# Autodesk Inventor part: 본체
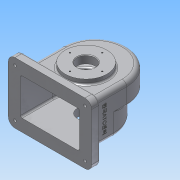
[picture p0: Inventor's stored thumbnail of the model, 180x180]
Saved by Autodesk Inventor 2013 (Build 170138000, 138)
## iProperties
Created: 2017-11
Part Number: 본체
Material: 알루미늄 6061
Document SubType Name: Modeling
Designer: Administrator
Density: 2.71 g/cm^3
Mass: 1079.49 g
Surface Area: 1182.07 cm^2
Volume: 398.335 cm^3
Author: Administrator
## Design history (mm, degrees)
sketch "스케치1"
  geometry: L1 (-58, 0)-(-58, -80); L2 (-58, -80)-(58, -80); L3 (58, -80)-(58, 0); A1 r 58 centre (0, 0) between (58, 0) and (-58, 0); 1 further point
  constraints: 6 end point, 2 point on circle, 2 tangent, 1 centre point, 1 coincident, 1 parallel, 1 perpendicular, 1 vertical
  dimensions: "d0" = 116 diameter of A1; "d1" = 80 distance from line of L2 A1.centre
extrude "돌출1" new body sketch "스케치1" distance "d2" = 38; taper "d3" = 0 deg
sketch "스케치2"
  geometry: L1 (-58, 0)-(-58, -80) reference; L2 (-58, -80)-(58, -80) reference; L3 (58, -80)-(58, 0) reference; L4 (-58, -23)-(-58, -80); L5 (58, -80)-(58, -23); L6 (58, -80)-(-58, -80); A1 r 58 centre (0, 0) between (58, 0) and (-58, 0) reference; A2 r 58 centre (0, -23) between (58, -23) and (-58, -23)
  constraints: 6 end point, 3 collinear, 2 point on circle, 2 point on line, 1 centre point, 1 vertical alignment
  dimensions: "d4" = 116 diameter of A2; "d5" = 57 distance from line of L2 A2.centre
extrude "돌출2" join sketch "스케치2" distance "d6" = 38; taper "d7" = 0 deg
feature "쉘1" dims "d10" = 5
fillet "모깎기3" dims "d11" = 8
fillet "모깎기4" dims "d12" = 3
sketch "스케치3"
  geometry: L1 (108, -8)-(108, -68) reference; L2 (0, 0)-(100, 0) reference; L3 (-8, -8)-(-8, -68) reference; L4 (100, -76)-(0, -76) reference; L5 (-25, 17)-(125, 17); L6 (125, 17)-(125, -93); L7 (125, -93)-(-25, -93); L8 (-25, -93)-(-25, 17); L9 (-25, 17)-(125, -93); L10 (125, 17)-(-25, -93); A1 r 8 centre (100, -68) between (100, -76) and (108, -68) reference; A2 r 8 centre (100, -8) between (108, -8) and (100, 0) reference; A3 r 8 centre (0, -8) between (0, 0) and (-8, -8) reference; A4 r 8 centre (0, -68) between (-8, -68) and (0, -76) reference; 1 further point
  constraints: 12 end point, 2 midpoint, 2 parallel, 1 horizontal, 1 perpendicular
  dimensions: "d13" = 150 distance of L6.end L7.end; "d14" = 110 distance of L5.end L6.end
extrude "돌출3" join sketch "스케치3" distance "d15" = 15; taper "d16" = 0 deg
fillet "모깎기5" dims "d17" = 12
fillet "모깎기6" dims "d18" = 3
sketch "스케치4"
  geometry: A1 r 9 centre (113, -5) between (113, -14) and (122, -5) reference; A2 r 9 centre (113, 81) between (122, 81) and (113, 90) reference; A3 r 9 centre (-13, 81) between (-13, 90) and (-22, 81) reference; A4 r 9 centre (-13, -5) between (-22, -5) and (-13, -14) reference; 5 further points
  constraints: 4 coincident
hole "구멍1" sketch "스케치4" at (-13, 81), (-13, -5), (113, -5), (113, 81) diameter "d19" = 5; stored, may be unused: countersink angle "d23" = 90 deg, drill point angle "d25" = 118 deg; dims "d20" = 6, "d21" = 12, "d22" = 5, "d24" = 8
sketch "스케치5"
  geometry: L1 (-63, -80)-(63, -80) reference; C1 r 37.5 at (0, -15); A1 r 50 centre (0, 0) between (50, 0) and (-50, 0) reference
  constraints: 1 centre point, 1 vertical alignment
  dimensions: "d26" = 75 diameter of C1; "d27" = 65 distance from line of L1 C1.centre
extrude "돌출4" join sketch "스케치5" distance "d28" = 9; taper "d29" = 0 deg
sketch "스케치7"
  geometry: L1 (-63, -80)-(63, -80) reference; C1 r 31 at (0, -15); 1 further point
  constraints: 1 centre point, 1 vertical alignment
  dimensions: "d30" = 62 diameter of C1; "d31" = 65 distance from line of L1 C1.centre
extrude "돌출5" join sketch "스케치7" distance "d32" = 10; taper "d33" = 0 deg
sketch "스케치8"
  geometry: C1 r 31 at (0, 0) reference; C2 r 16 at (0, 0); 1 further point
  constraints: 1 centre point, 1 coincident
  dimensions: "d34" = 32 diameter of C2
extrude "돌출6" cut sketch "스케치8" stored distance "d35" = 10; taper "d36" = 0 deg
sketch "스케치9"
  geometry: C1 r 16 at (0, 0) reference; 2 further points
  constraints: 1 vertical alignment
  dimensions: "d37" = 29 distance of C1.centre point (0, 29)
hole "구멍2" sketch "스케치9" at (0, 29) diameter "d38" = 2.459; stored, may be unused: countersink angle "d42" = 90 deg, drill point angle "d44" = 118 deg; dims "d39" = 6, "d40" = 12, "d41" = 5, "d43" = 8
sketch "스케치10"
  geometry: C1 r 16 at (0, 0) reference; 2 further points
  constraints: 1 vertical alignment
  dimensions: "d48" = 26 distance of C1.centre point (0, 26)
hole "구멍3" sketch "스케치10" at (0, 26) diameter "d49" = 2.459; stored, may be unused: countersink angle "d53" = 90 deg, drill point angle "d55" = 118 deg; dims "d50" = 6, "d51" = 12, "d52" = 5, "d54" = 8
fillet "모깎기7" dims "d59" = 3
chamfer "모따기1" distance "d60" = 1; stored, may be unused: second distance "d61" = 2, angle "d62" = 45 deg
node "작업 평면1"
sketch "스케치11"
  geometry: L1 (-113, 93)-(-13, 93) reference; C1 r 6 at (-63, 74); 1 further point
  constraints: 1 centre point, 1 vertical alignment
  dimensions: "d64" = 12 diameter of C1; "d65" = 19 distance from line of L1 C1.centre
extrude "돌출7" join sketch "스케치11" stored distance "d66" = 10; taper "d67" = 0 deg
sketch "스케치12"
  geometry: C1 r 6 at (0, 0) reference; 2 further points
  constraints: 1 coincident
hole "구멍4" sketch "스케치12" at (0, 0) diameter "d68" = 4.459; stored, may be unused: countersink angle "d72" = 90 deg, drill point angle "d74" = 118 deg; dims "d69" = 6, "d70" = 12, "d71" = 5, "d73" = 8
fillet "모깎기8" dims "d75" = 3
sketch "스케치13"
  geometry: L1 (-35, 23)-(-35, -39) reference; L2 (-40, -57)-(-52, -57) reference; 2 further points
  constraints: 1 other
  dimensions: "d76" = 38 distance from line of L1 point (3, -17); "d77" = 40 distance from line of L2 point (3, -17)
feature "엠보싱1" sketch "스케치13" dims "d78" = 0.5, "d79" = 0
node "솔리드1"
pattern_circular "원형 패턴1" dims angle "d46" = 360 deg
pattern_circular "원형 패턴2" dims angle "d57" = 360 deg
other parameters: "d63" = -144
